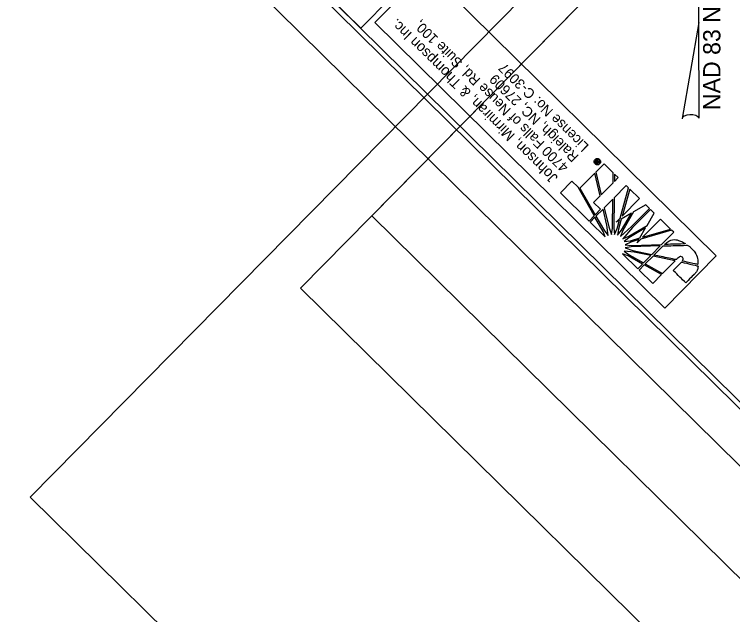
# Model space of a CAD drawing. Extents: x 1265903 to 1267873, y 771347 to 773361.
# Drawn here: x 1265903.3 to 1266256.5, y 772103.6 to 772398.9 of the extents above; entities that cross this region are included whole.
import ezdxf

# ---------------------------------------------------------------- set-up
doc = ezdxf.new("R2010")
doc.units = 0
for name, color, linetype in [('Exist Roads EOT', 7, 'Continuous'), ('Prop Conc 1ft 6in Curb and Gutter', 7, 'Continuous'), ('Prop Conc 4in Sidewalk', 7, 'Continuous'), ('Prop Drainage Structure Drop Inlet Grate 2 Narrow Slots and Sag Grates 840 24 Label', 7, 'Continuous'), ('Prop EOT', 7, 'Continuous'), ('Prop Horizontal Alignment Station Label', 7, 'Continuous'), ('Prop Plan Preparation Crest', 7, 'Continuous'), ('Prop Plan Preparation Watershed Post Construction', 7, 'Continuous'), ('Typical Terminator CELL', 7, 'Continuous')]:
    doc.layers.add(name, color=color, linetype=linetype)

msp = doc.modelspace()

# ---------------------------------------------------------------- linework, layer by layer
at = {"layer": 'Exist Roads EOT'}
for p, q in [((1266239.92, 772394.96), (1266239.92, 772421.16)), ((1266239.92, 772394.96), (1266231.57, 772347.71)), ((1266239.97, 772347.91), (1266239.92, 772394.96))]:
    msp.add_line(p, q, dxfattribs=at)
msp.add_ellipse((1266235.81, 772347.54), major_axis=(4.23, -0.03), ratio=0.461098, start_param=0.201328, end_param=3.141593, dxfattribs=at)
at = {"layer": 'Prop Conc 1ft 6in Curb and Gutter'}
for p, q in [((1266073.64, 772392.09), (1265931.14, 772532.52)), ((1266099.97, 772418.88), (1266073.64, 772392.09))]:
    msp.add_line(p, q, dxfattribs=at)
msp.add_lwpolyline([(1265931.14, 772532.52), (1266999.64, 771479.71), (1267736.59, 772227.64), (1266668.1, 773280.44)], close=True, dxfattribs=at)
at = {"layer": 'Prop Conc 4in Sidewalk'}
for p, q in [((1267092.63, 773360.64), (1265911.05, 772161.45)), ((1265911.05, 772161.45), (1266691.04, 771392.92))]:
    msp.add_line(p, q, dxfattribs=at)
at = {"layer": 'Prop Drainage Structure Drop Inlet Grate 2 Narrow Slots and Sag Grates 840 24 Label'}
for p, q in [((1266190.83, 772327.36), (1266190.82, 772327.36)), ((1266190.83, 772327.36), (1266191.05, 772327.58)), ((1266191.05, 772327.58), (1266190.83, 772327.36)), ((1266191.04, 772327.59), (1266191.05, 772327.58)), ((1266188.84, 772325.33), (1266189.05, 772325.55)), ((1266189.05, 772325.55), (1266188.84, 772325.33)), ((1266193.23, 772325.45), (1266189.16, 772321.31)), ((1266189.43, 772325.94), (1266189.37, 772326)), ((1266189.43, 772325.94), (1266189.62, 772326.13)), ((1266189.62, 772326.13), (1266189.43, 772325.94)), ((1266189.85, 772325.53), (1266189.43, 772325.94)), ((1266189.59, 772326.16), (1266189.62, 772326.13)), ((1266189.62, 772326.13), (1266189.81, 772325.95)), ((1266189.81, 772325.95), (1266190.05, 772326.19)), ((1266190.85, 772326.55), (1266189.85, 772325.53)), ((1266189.86, 772326.37), (1266189.85, 772326.38)), ((1266189.86, 772326.37), (1266190.04, 772326.56)), ((1266190.04, 772326.56), (1266189.86, 772326.37)), ((1266190.05, 772326.19), (1266189.86, 772326.37)), ((1266190.03, 772326.57), (1266190.04, 772326.56)), ((1266190.04, 772326.56), (1266190.23, 772326.38)), ((1266190.23, 772326.38), (1266190.62, 772326.77)), ((1266190.62, 772326.77), (1266190.85, 772326.55)), ((1266197.76, 772321), (1266193.23, 772325.45)), ((1266188.65, 772320.79), (1266181.4, 772313.42)), ((1266191.25, 772309.6), (1266188.65, 772320.79)), ((1266189.16, 772321.31), (1266191.79, 772310.15)), ((1266197.67, 772316.12), (1266197.76, 772321)), ((1266198.42, 772320.35), (1266198.3, 772316.77)), ((1266200.15, 772318.65), (1266198.42, 772320.35)), ((1266177.46, 772316.8), (1266171.81, 772311.05)), ((1266180.45, 772313.86), (1266177.46, 772316.8)), ((1266198.3, 772316.77), (1266200.15, 772318.65)), ((1266188.45, 772299.9), (1266180.45, 772313.86)), ((1266181.4, 772313.42), (1266188.84, 772300.3)), ((1266191.79, 772310.15), (1266197.67, 772316.12)), ((1266204.13, 772314.72), (1266198.24, 772308.73)), ((1266201.13, 772298.65), (1266205.31, 772313.57)), ((1266205.31, 772313.57), (1266204.13, 772314.72)), ((1266171.81, 772311.05), (1266185.84, 772297.25)), ((1266188.1, 772306.4), (1266191.25, 772309.6)), ((1266205.83, 772312.99), (1266202.07, 772299.61)), ((1266210.61, 772308.29), (1266205.83, 772312.99)), ((1266191.53, 772303.03), (1266188.1, 772306.4)), ((1266197.56, 772308.04), (1266193.36, 772303.77)), ((1266197.34, 772293.76), (1266197.56, 772308.04)), ((1266198.24, 772308.73), (1266197.96, 772293.8)), ((1266202.07, 772299.61), (1266210.61, 772308.29)), ((1266188.88, 772300.34), (1266191.53, 772303.03)), ((1266192.77, 772303.17), (1266189.25, 772299.68)), ((1266194.67, 772295.23), (1266192.77, 772303.17)), ((1266193.36, 772303.77), (1266195.51, 772294.48)), ((1266206.8, 772294.53), (1266215.55, 772303.43)), ((1266216.03, 772302.96), (1266207.28, 772294.06)), ((1266213.7, 772305.25), (1266207.79, 772301.81)), ((1266215.55, 772303.43), (1266213.7, 772305.25)), ((1266217.86, 772301.16), (1266216.03, 772302.96)), ((1266185.84, 772297.25), (1266188.37, 772299.82)), ((1266188.75, 772299.17), (1266186.39, 772296.77)), ((1266188.37, 772299.82), (1266188.45, 772299.9)), ((1266192.75, 772292.18), (1266188.75, 772299.17)), ((1266188.84, 772300.3), (1266188.88, 772300.34)), ((1266189.25, 772299.68), (1266193.42, 772292.48)), ((1266206.7, 772301.15), (1266201.65, 772298.14)), ((1266201.8, 772292.71), (1266206.7, 772301.15)), ((1266207.79, 772301.81), (1266202.5, 772292.6)), ((1266214.38, 772295.12), (1266217.86, 772301.16)), ((1266186.39, 772296.77), (1266193.76, 772289.46)), ((1266199.21, 772296.7), (1266201.13, 772298.65)), ((1266200.86, 772297.69), (1266199.21, 772296.7)), ((1266199.68, 772293.63), (1266200.86, 772297.69)), ((1266201.65, 772298.14), (1266200.3, 772293.32)), ((1266220.91, 772298.23), (1266212.2, 772289.29)), ((1266225.89, 772293.33), (1266220.91, 772298.23)), ((1266193.76, 772289.46), (1266192.75, 772292.18)), ((1266193.42, 772292.48), (1266195.22, 772290.19)), ((1266195.22, 772290.19), (1266194.67, 772295.23)), ((1266195.51, 772294.48), (1266196.82, 772290.65)), ((1266196.82, 772290.65), (1266197.34, 772293.76)), ((1266197.96, 772293.8), (1266198.39, 772290.69)), ((1266198.39, 772290.69), (1266199.68, 772293.63)), ((1266200.3, 772293.32), (1266199.92, 772290.35)), ((1266199.92, 772290.35), (1266201.8, 772292.71)), ((1266201.28, 772289.6), (1266206.8, 772294.53)), ((1266202.5, 772292.6), (1266201.28, 772289.6)), ((1266207.28, 772294.06), (1266202.39, 772288.52)), ((1266205.4, 772289.75), (1266214.38, 772295.12)), ((1266213.69, 772293.97), (1266205.41, 772289.01)), ((1266210.81, 772288.91), (1266213.69, 772293.97)), ((1266226.4, 772292.82), (1266211.26, 772288.33)), ((1266212.2, 772289.29), (1266225.89, 772293.33)), ((1266227.5, 772291.74), (1266226.4, 772292.82)), ((1266202.39, 772288.52), (1266205.4, 772289.75)), ((1266205.41, 772289.01), (1266203.19, 772287.13)), ((1266206.18, 772287.53), (1266210.81, 772288.91)), ((1266211.26, 772288.33), (1266209.52, 772286.57)), ((1266221.55, 772285.68), (1266227.5, 772291.74)), ((1266203.19, 772287.13), (1266206.18, 772287.53)), ((1266206.48, 772286.93), (1266203.57, 772285.6)), ((1266203.57, 772285.6), (1266206.68, 772285.22)), ((1266210.38, 772288.1), (1266206.48, 772286.93)), ((1266220.85, 772284.98), (1266206.61, 772284.57)), ((1266206.68, 772285.22), (1266221.55, 772285.68)), ((1266209.52, 772286.57), (1266210.38, 772288.1)), ((1266216.76, 772280.81), (1266220.85, 772284.98)), ((1266208.05, 772281.99), (1266203.08, 772282.46)), ((1266203.08, 772282.46), (1266205.52, 772280.58)), ((1266206.61, 772284.57), (1266203.55, 772284.04)), ((1266203.55, 772284.04), (1266207.36, 772282.82)), ((1266207.36, 772282.82), (1266216.76, 772280.81)), ((1266216.19, 772280.23), (1266208.05, 772281.99)), ((1266205.01, 772280.06), (1266202.26, 772281.1)), ((1266202.26, 772281.1), (1266209.77, 772273.71)), ((1266212.12, 772276.1), (1266205.01, 772280.06)), ((1266205.52, 772280.58), (1266212.63, 772276.62)), ((1266212.63, 772276.62), (1266216.19, 772280.23)), ((1266217.31, 772279.99), (1266213.51, 772276.12)), ((1266228.15, 772277.65), (1266217.31, 772279.99)), ((1266209.77, 772273.71), (1266212.12, 772276.1)), ((1266213.03, 772275.64), (1266210.5, 772273.06)), ((1266221.53, 772270.92), (1266213.03, 772275.64)), ((1266213.51, 772276.12), (1266222.03, 772271.43)), ((1266222.03, 772271.43), (1266228.15, 772277.65)), ((1266210.5, 772273.06), (1266217.17, 772266.5)), ((1266217.17, 772266.5), (1266221.53, 772270.92))]:
    msp.add_line(p, q, dxfattribs=at)
msp.add_lwpolyline([(1266248.42, 772280.17), (1266105.93, 772420.57), (1266080.59, 772394.85), (1266223.08, 772254.46)], close=True, dxfattribs=at)
for points in [[(1266189.75, 772327.15), (1266189.81, 772327.21), (1266189.83, 772327.26), (1266189.87, 772327.29), (1266189.95, 772327.43), (1266190.17, 772327.22)], [(1266191.79, 772310.15), (1266197.67, 772316.12), (1266197.76, 772321), (1266193.23, 772325.45), (1266189.16, 772321.31), (1266191.79, 772310.15), (1266191.79, 772310.15)], [(1266188.84, 772300.3), (1266188.88, 772300.34), (1266191.53, 772303.03), (1266188.1, 772306.4), (1266191.25, 772309.6), (1266188.65, 772320.79), (1266181.4, 772313.42), (1266188.84, 772300.3)], [(1266200.15, 772318.65), (1266200.15, 772318.65), (1266198.42, 772320.35), (1266198.3, 772316.77), (1266200.15, 772318.65)], [(1266171.81, 772311.05), (1266185.84, 772297.25), (1266188.37, 772299.82), (1266188.45, 772299.9), (1266180.45, 772313.86), (1266177.46, 772316.8), (1266171.81, 772311.05)], [(1266198.39, 772290.69), (1266199.68, 772293.63), (1266200.86, 772297.69), (1266199.21, 772296.7), (1266201.13, 772298.65), (1266205.31, 772313.57), (1266204.13, 772314.72), (1266198.24, 772308.73), (1266197.96, 772293.8), (1266198.39, 772290.69)], [(1266210.61, 772308.29), (1266205.83, 772312.99), (1266202.07, 772299.61), (1266210.61, 772308.29)], [(1266196.82, 772290.65), (1266197.34, 772293.76), (1266197.56, 772308.04), (1266193.36, 772303.77), (1266195.51, 772294.48), (1266196.82, 772290.65)], [(1266195.22, 772290.19), (1266194.67, 772295.23), (1266192.77, 772303.17), (1266189.25, 772299.68), (1266193.42, 772292.48), (1266195.22, 772290.19)], [(1266201.28, 772289.6), (1266206.8, 772294.53), (1266215.55, 772303.43), (1266213.7, 772305.25), (1266207.79, 772301.81), (1266202.5, 772292.6), (1266201.28, 772289.6)], [(1266205.4, 772289.75), (1266214.38, 772295.12), (1266217.86, 772301.16), (1266216.03, 772302.96), (1266207.28, 772294.06), (1266202.39, 772288.52), (1266205.4, 772289.75)], [(1266192.75, 772292.18), (1266188.75, 772299.17), (1266186.39, 772296.77), (1266193.76, 772289.46), (1266192.75, 772292.18)], [(1266199.92, 772290.35), (1266201.8, 772292.71), (1266206.7, 772301.15), (1266201.65, 772298.14), (1266200.3, 772293.32), (1266199.92, 772290.35)], [(1266225.89, 772293.33), (1266220.91, 772298.23), (1266212.2, 772289.29), (1266225.89, 772293.33)], [(1266203.19, 772287.13), (1266206.18, 772287.53), (1266210.81, 772288.91), (1266213.69, 772293.97), (1266205.41, 772289.01), (1266203.19, 772287.13)], [(1266203.57, 772285.6), (1266206.68, 772285.22), (1266221.55, 772285.68), (1266227.5, 772291.74), (1266226.4, 772292.82), (1266211.26, 772288.33), (1266209.52, 772286.57), (1266210.38, 772288.1), (1266206.48, 772286.93), (1266203.57, 772285.6)], [(1266216.76, 772280.81), (1266220.85, 772284.98), (1266206.61, 772284.57), (1266203.55, 772284.04), (1266207.36, 772282.82), (1266216.76, 772280.81)], [(1266212.63, 772276.62), (1266216.19, 772280.23), (1266208.05, 772281.99), (1266203.08, 772282.46), (1266205.52, 772280.58), (1266212.63, 772276.62)], [(1266205.01, 772280.06), (1266202.26, 772281.1), (1266209.77, 772273.71), (1266212.12, 772276.1), (1266205.01, 772280.06)], [(1266228.15, 772277.65), (1266217.31, 772279.99), (1266213.51, 772276.12), (1266222.03, 772271.43), (1266228.15, 772277.65)], [(1266221.53, 772270.92), (1266213.03, 772275.64), (1266210.5, 772273.06), (1266217.17, 772266.5), (1266221.53, 772270.92)]]:
    msp.add_lwpolyline(points, dxfattribs=at)
for points, degree in [([(1266188.84, 772325.33), (1266188.52, 772325.64), (1266188.36, 772326.02), (1266188.35, 772326.45), (1266188.33, 772326.87), (1266188.48, 772327.25), (1266188.79, 772327.57)], 3), ([(1266190.82, 772327.36), (1266190.57, 772327.61), (1266190.27, 772327.74), (1266189.92, 772327.73), (1266189.57, 772327.73), (1266189.26, 772327.6), (1266189.01, 772327.35), (1266188.77, 772327.1), (1266188.64, 772326.79), (1266188.64, 772326.44), (1266188.66, 772326.1), (1266188.79, 772325.8), (1266189.05, 772325.55)], 3), ([(1266188.79, 772327.57), (1266189.1, 772327.88), (1266189.48, 772328.04), (1266189.91, 772328.06), (1266190.34, 772328.05), (1266190.72, 772327.9), (1266191.04, 772327.59)], 3), ([(1266191.05, 772327.58), (1266191.35, 772327.28), (1266191.51, 772326.9), (1266191.52, 772326.46), (1266191.53, 772326.03), (1266191.37, 772325.65), (1266191.06, 772325.33), (1266190.75, 772325.02), (1266190.38, 772324.86), (1266189.96, 772324.87), (1266189.52, 772324.88), (1266189.15, 772325.02), (1266188.84, 772325.33)], 3), ([(1266189.05, 772325.55), (1266189.3, 772325.3), (1266189.59, 772325.17), (1266189.93, 772325.17), (1266190.28, 772325.17), (1266190.6, 772325.3), (1266190.84, 772325.55), (1266191.09, 772325.8), (1266191.21, 772326.12), (1266191.21, 772326.47), (1266191.21, 772326.82), (1266191.08, 772327.11), (1266190.83, 772327.36)], 3), ([(1266190.17, 772327.22), (1266190.14, 772327.14), (1266190.1, 772327.06), (1266190.03, 772326.99), (1266189.94, 772326.9), (1266189.89, 772326.83), (1266189.89, 772326.78)], 3), ([(1266189.37, 772326), (1266189.11, 772326.26), (1266189.08, 772326.49), (1266189.28, 772326.69), (1266189.37, 772326.78), (1266189.48, 772326.82), (1266189.62, 772326.79)], 3), ([(1266189.85, 772326.38), (1266189.7, 772326.53), (1266189.58, 772326.55), (1266189.5, 772326.47), (1266189.43, 772326.4), (1266189.46, 772326.29), (1266189.59, 772326.16)], 3), ([(1266189.62, 772326.79), (1266189.59, 772326.89), (1266189.63, 772327.01), (1266189.75, 772327.15)], 2), ([(1266189.89, 772326.78), (1266189.9, 772326.73), (1266189.94, 772326.66), (1266190.03, 772326.57)], 2), ([(1266222.97, 772285.74), (1266222.97, 772285.74), (1266233.44, 772285.99), (1266233.44, 772285.99), (1266230.28, 772287.86), (1266226.09, 772288.67), (1266222.97, 772285.74)], 3), ([(1266231.76, 772279.41), (1266232.15, 772279.02), (1266232.28, 772278.46), (1266231.7, 772277.59), (1266231.7, 772277.59), (1266239.4, 772275.84), (1266239.4, 772275.84), (1266239.45, 772278.84), (1266238.01, 772282.08), (1266236.01, 772284.04), (1266235.49, 772284.55), (1266235.05, 772284.9), (1266234.4, 772285.33), (1266234.4, 772285.33), (1266222.27, 772285.03), (1266222.27, 772285.03), (1266222.27, 772285.03), (1266217.85, 772280.54), (1266217.85, 772280.54), (1266217.85, 772280.54), (1266228.7, 772278.22), (1266228.7, 772278.22), (1266230.36, 772279.9), (1266231.21, 772279.95), (1266231.76, 772279.41)], 3), ([(1266231.76, 772279.41), (1266232.15, 772279.02), (1266232.28, 772278.46), (1266231.7, 772277.59), (1266231.7, 772277.59), (1266239.4, 772275.84), (1266239.4, 772275.84), (1266239.45, 772278.84), (1266238.01, 772282.08), (1266236.01, 772284.04), (1266235.49, 772284.55), (1266235.05, 772284.9), (1266234.4, 772285.33), (1266234.4, 772285.33), (1266222.27, 772285.03), (1266222.27, 772285.03), (1266222.27, 772285.03), (1266217.85, 772280.54), (1266217.85, 772280.54), (1266217.85, 772280.54), (1266228.7, 772278.22), (1266228.7, 772278.22), (1266230.36, 772279.9), (1266231.21, 772279.95), (1266231.76, 772279.41)], 3), ([(1266227.25, 772272.91), (1266227.25, 772272.91), (1266233.43, 772266.83), (1266233.43, 772266.83), (1266233.43, 772266.83), (1266237.23, 772270.7), (1266237.23, 772270.7), (1266237.23, 772270.7), (1266237.63, 772271.1), (1266237.63, 772271.1), (1266238.82, 772272.31), (1266239.37, 772273.66), (1266239.45, 772275.16), (1266239.45, 772275.16), (1266231.34, 772277.07), (1266231.26, 772276.99), (1266231.26, 772276.99), (1266227.25, 772272.91), (1266227.25, 772272.91)], 3)]:
    msp.add_open_spline(points, degree=degree, dxfattribs=at)
at = {"layer": 'Prop EOT'}
msp.add_lwpolyline([(1267847.69, 772121.71), (1266660.96, 773290.98), (1265920.5, 772539.5), (1267107.23, 771370.21)], close=True, dxfattribs=at)
at = {"layer": 'Prop Horizontal Alignment Station Label'}
msp.add_lwpolyline([(1267870.98, 772126.83), (1266671.79, 773308.41), (1265903.26, 772528.42), (1267102.45, 771346.84)], close=True, dxfattribs=at)
at = {"layer": 'Prop Plan Preparation Crest'}
msp.add_lwpolyline([(1266043.92, 772264.22), (1266791.85, 771527.31), (1267844.64, 772595.79), (1267247.35, 773184.3), (1267079.43, 773013.88), (1266928.79, 773162.31)], close=True, dxfattribs=at)
at = {"layer": 'Prop Plan Preparation Watershed Post Construction'}
msp.add_lwpolyline([(1266826.95, 771562.93), (1267809.56, 772560.18), (1267212.27, 773148.7), (1267079.43, 773013.88), (1266928.79, 773162.31), (1266079.01, 772299.87)], close=True, dxfattribs=at)
at = {"layer": 'Typical Terminator CELL'}
msp.add_lwpolyline([(1266826.95, 771562.93), (1267809.56, 772560.18), (1267212.27, 773148.7), (1267079.43, 773013.88), (1266928.79, 773162.31), (1266079.01, 772299.87)], close=True, dxfattribs=at)

# ---------------------------------------------------------------- texts
at = {"layer": 'Exist Roads EOT'}
msp.add_text('NAD 83 NA 2011', height=8.5, rotation=90, dxfattribs=at).set_placement((1266250.44, 772351.82))
at = {"layer": 'Prop Drainage Structure Drop Inlet Grate 2 Narrow Slots and Sag Grates 840 24 Label'}
for s, height, p in [('Johnson, Mirmiran, & Thompson Inc.', 5.1112, (1266170.89, 772318.86)), ('4700 Falls of Neuse Rd, Suite 100, ', 4.9652, (1266176.16, 772324.2)), ('License No: C-3097', 4.9652, (1266186.12, 772334.31)), ('Raleigh, NC, 27609', 4.9652, (1266181.14, 772329.26))]:
    msp.add_text(s, height=height, rotation=135.4239, dxfattribs=at).set_placement(p)

doc.saveas('drawing.dxf')
